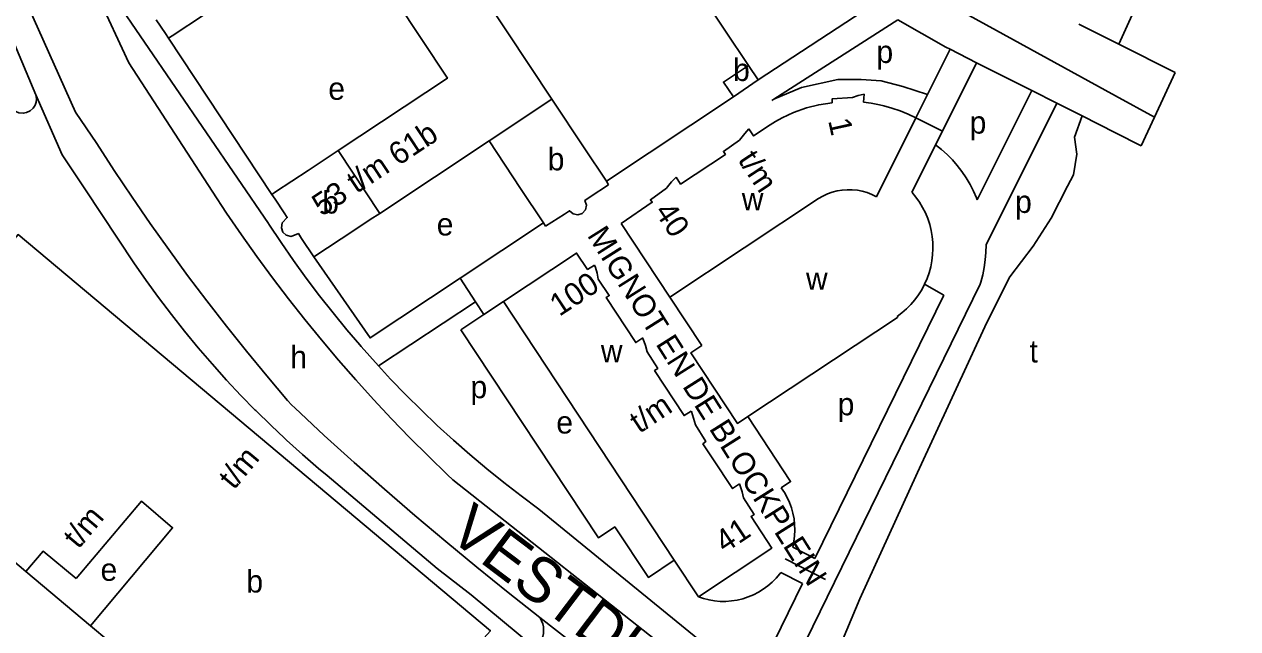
# Model space of a CAD drawing. Extents: x 160673 to 161924, y 382258 to 384145.
# Drawn here: x 161632.6 to 161848.9, y 383061.6 to 383169.3 of the extents above; entities that cross this region are included whole.
import ezdxf

# ---------------------------------------------------------------- set-up
doc = ezdxf.new("R2010")
doc.units = 0
for name, color, linetype in [('BLT_Basislijn', 7, 'Continuous'), ('BLT_Bebouwing', 7, 'Continuous'), ('BLT_Centroide', 7, 'Continuous'), ('BLT_Huisnummer_reeks', 7, 'Continuous'), ('BLT_Onderdoorgang_en_onderverdeling', 7, 'Continuous'), ('BLT_Onderverdeling_panden', 7, 'Continuous'), ('BLT_Straatnaam_hoofdweg', 7, 'Continuous'), ('BLT_Straatnaam_verkleind', 7, 'Continuous'), ('BLT_Vlakafsluiter', 7, 'Continuous')]:
    doc.layers.add(name, color=color, linetype=linetype)

msp = doc.modelspace()

# ---------------------------------------------------------------- linework, layer by layer
at = {"layer": 'BLT_Basislijn'}
for p, q in [((161676.17, 383133.8), (161644.31, 383180.4)), ((161763.41, 383159.38), (161783.67, 383172.63)), ((161766.2, 383155.97), (161788.32, 383170.08)), ((161827.12, 383166.05), (161820.55, 383169.32)), ((161676.76, 383139), (161658.36, 383166.81)), ((161827.69, 383165.77), (161827.12, 383166.05)), ((161793.58, 383156.77), (161797.62, 383164.84)), ((161797.62, 383164.84), (161802.36, 383162.45)), ((161666.12, 383139.57), (161651.29, 383162.43)), ((161796.26, 383150.28), (161802.36, 383162.45)), ((161812.19, 383157.5), (161802.46, 383138.05)), ((161812.19, 383157.5), (161816.65, 383155.25)), ((161634.69, 383156.74), (161639.36, 383146.05)), ((161759.04, 383156.37), (161736.37, 383141.33)), ((161765.85, 383155.74), (161766.2, 383155.97)), ((161791.51, 383152.65), (161793.58, 383156.77)), ((161816.65, 383155.25), (161804.03, 383130)), ((161816.65, 383155.25), (161821.16, 383152.98)), ((161821.16, 383152.98), (161819.83, 383149.18)), ((161821.16, 383152.98), (161827.12, 383149.98)), ((161827.12, 383149.98), (161831.7, 383147.66)), ((161639.36, 383146.05), (161643.52, 383139.82)), ((161643.52, 383139.82), (161652.16, 383126.81)), ((161725.14, 383133.94), (161710.34, 383124.06)), ((161710.34, 383124.06), (161713.07, 383119.87)), ((161802.97, 383122.97), (161766.55, 383048.54)), ((161793.09, 383122.98), (161796.51, 383121.02)), ((161796.51, 383121.02), (161773.53, 383074.14)), ((161695.77, 383108.42), (161713.07, 383119.87)), ((161713.07, 383119.87), (161714.55, 383117.6)), ((161714.55, 383117.6), (161718.02, 383119.89)), ((161710.43, 383114.87), (161714.55, 383117.6)), ((161686.59, 383088.93), (161706.21, 383072.34)), ((161774.99, 383036.07), (161709.02, 383088.14)), ((161762.58, 383051.8), (161724.31, 383082.94)), ((161773.53, 383074.14), (161769.59, 383076.17)), ((161775.42, 383070.36), (161768.26, 383074.05)), ((161632.93, 383071.83), (161644.46, 383062.15)), ((161771.33, 383069.65), (161767.46, 383071.65)), ((161771.33, 383069.65), (161762.58, 383051.8))]:
    msp.add_line(p, q, dxfattribs=at)
for points in [[(161665.14, 383245.7), (161705.82, 383223.19), (161827.12, 383156.57)], [(161846.82, 383218.48), (161848.89, 383212.43), (161827.69, 383165.77)], [(161617.1, 383208.61), (161641.78, 383153.62), (161645.56, 383148.03), (161648.67, 383143.25), (161651.84, 383138.51), (161655.08, 383133.82), (161658.38, 383129.17), (161661.75, 383124.57), (161665.19, 383120.02), (161668.68, 383115.51), (161672.25, 383111.06), (161675.87, 383106.65), (161679.55, 383102.3), (161680.29, 383101.44)], [(161742.19, 383190.52), (161753.26, 383174.57), (161761.69, 383161.98)], [(161651.29, 383162.43), (161645.75, 383174.39), (161644.31, 383180.4)], [(161788.32, 383170.08), (161796.9, 383165.21), (161797.62, 383164.84)], [(161827.69, 383165.77), (161837.77, 383160.71)], [(161802.36, 383162.45), (161812.19, 383157.5)], [(161766.2, 383155.97), (161771.16, 383158.04), (161777.63, 383159.44), (161781.78, 383159.45), (161785.34, 383159.21), (161789.23, 383158.19), (161793.58, 383156.77)], [(161827.12, 383156.57), (161834.07, 383152.75)], [(161819.83, 383149.18), (161820.21, 383146.13), (161819.64, 383142.5), (161818.55, 383140.46), (161815.64, 383134.73), (161812.46, 383129.75), (161808.28, 383124.28), (161804.19, 383116.19), (161791.81, 383089.44), (161781.57, 383066.96), (161775.34, 383052.22)], [(161795.04, 383147.83), (161796.09, 383146.99), (161797.09, 383146.09), (161798.03, 383145.13), (161798.91, 383144.11), (161799.73, 383143.05), (161800.49, 383141.94), (161801.18, 383140.78), (161801.8, 383139.59), (161802.34, 383138.36), (161802.46, 383138.05)], [(161666.12, 383139.57), (161668.7, 383135.64), (161671.35, 383131.76), (161674.07, 383127.93), (161676.85, 383124.14), (161679.7, 383120.4), (161682.61, 383116.71), (161685.58, 383113.07), (161688.61, 383109.48), (161691.7, 383105.94), (161694.86, 383102.45), (161698.07, 383099.02), (161701.34, 383095.65), (161704.67, 383092.33), (161708.05, 383089.06), (161709.02, 383088.14)], [(161692.41, 383112.19), (161690.14, 383114.85), (161687.66, 383117.87), (161685.25, 383120.94), (161682.9, 383124.06), (161680.61, 383127.23), (161678.39, 383130.44), (161676.24, 383133.7), (161676.17, 383133.8)], [(161804.03, 383130), (161804, 383128.66), (161803.89, 383127.32), (161803.7, 383125.98), (161803.44, 383124.67), (161803.09, 383123.37), (161802.97, 383122.97)], [(161684.23, 383127.86), (161694.27, 383113.42), (161710.34, 383124.06)], [(161652.16, 383126.81), (161654.33, 383123.68), (161656.55, 383120.61), (161657.32, 383119.6)], [(161657.32, 383119.6), (161658.85, 383117.58), (161661.21, 383114.6), (161663.62, 383111.67), (161666.11, 383108.79), (161668.68, 383105.91)], [(161748.47, 383073.84), (161743.86, 383070.77), (161737.86, 383079.76), (161734.95, 383077.83), (161710.43, 383114.87)], [(161695.77, 383108.42), (161692.68, 383111.88), (161692.41, 383112.19)], [(161724.31, 383082.94), (161721.18, 383085.27), (161718.09, 383087.66), (161715.05, 383090.12), (161712.06, 383092.63), (161709.13, 383095.21), (161706.24, 383097.84), (161703.42, 383100.54), (161700.65, 383103.29), (161697.93, 383106.1), (161695.77, 383108.42)], [(161668.68, 383105.91), (161671.25, 383103.19), (161673.81, 383100.57)], [(161724.52, 383063.62), (161718.88, 383068.07), (161713.29, 383072.58), (161707.75, 383077.16), (161702.26, 383081.79), (161696.82, 383086.49), (161691.44, 383091.24), (161686.11, 383096.06), (161680.83, 383100.94), (161680.29, 383101.44)], [(161673.81, 383100.57), (161673.9, 383100.47), (161676.62, 383097.81), (161679.02, 383095.56)], [(161761.61, 383099.44), (161769.19, 383087.83), (161767.54, 383086.74)], [(161679.02, 383095.56), (161679.39, 383095.21), (161682.21, 383092.67), (161685.09, 383090.18), (161686.59, 383088.93)], [(161769.59, 383076.17), (161769.8, 383077.16), (161769.92, 383078.17), (161769.97, 383079.17), (161769.93, 383080.18), (161769.82, 383081.19), (161769.63, 383082.18), (161769.36, 383083.15), (161769.01, 383084.1), (161768.59, 383085.02), (161768.1, 383085.9), (161767.54, 383086.74)], [(161723.47, 383058.38), (161712.3, 383067.64), (161706.21, 383072.34)], [(161752.77, 383067.31), (161753.69, 383066.98), (161754.67, 383066.74), (161755.67, 383066.58), (161756.68, 383066.49), (161757.69, 383066.49), (161758.7, 383066.57), (161759.7, 383066.73), (161760.68, 383066.97), (161761.64, 383067.28), (161762.57, 383067.67), (161763.47, 383068.13), (161764.33, 383068.66), (161765.15, 383069.26), (161765.91, 383069.92), (161766.62, 383070.63), (161767.27, 383071.41), (161767.46, 383071.65)], [(161724.11, 383058.83), (161724.56, 383059.31), (161724.83, 383059.69), (161725.03, 383060.23), (161725.15, 383060.79), (161725.19, 383061.36), (161725.15, 383061.94), (161725.03, 383062.5), (161724.83, 383063.04), (161724.52, 383063.62)]]:
    msp.add_lwpolyline(points, dxfattribs=at)
at = {"layer": 'BLT_Bebouwing'}
for p, q in [((161761.69, 383161.98), (161763.41, 383159.38)), ((161763.41, 383159.38), (161759.04, 383156.37)), ((161726.68, 383155.97), (161732.44, 383147.27)), ((161782.17, 383155.43), (161782.3, 383156.82)), ((161715.49, 383148.55), (161695.98, 383135.61)), ((161721.09, 383140.06), (161715.49, 383148.55)), ((161732.44, 383147.27), (161736.37, 383141.33)), ((161795.04, 383147.83), (161792.77, 383143.26)), ((161792.77, 383143.26), (161790.84, 383139.37)), ((161725.14, 383133.94), (161721.09, 383140.06)), ((161736.78, 383140.7), (161733.47, 383138.54)), ((161736.37, 383141.33), (161736.78, 383140.7)), ((161694.29, 383134.49), (161695.98, 383135.61)), ((161725.54, 383133.33), (161725.14, 383133.94)), ((161728.89, 383135.47), (161725.54, 383133.33)), ((161739, 383133.78), (161747.66, 383120.71)), ((161747.66, 383120.71), (161753.36, 383112.08)), ((161748.47, 383073.84), (161718.02, 383119.89)), ((161632.93, 383071.83), (161605.39, 383094.94)), ((161752.77, 383067.31), (161748.47, 383073.84)), ((161682.18, 383030.53), (161644.46, 383062.15))]:
    msp.add_line(p, q, dxfattribs=at)
for points in [[(161692.21, 383207.98), (161709.38, 383182.09), (161709.93, 383182.91), (161711.09, 383183.14), (161712.15, 383182.42), (161712.4, 383181.2), (161711.69, 383180.19), (161710.74, 383180.02), (161726.68, 383155.97)], [(161688.57, 383146.81), (161708.05, 383159.68), (161689.63, 383187.5), (161670.15, 383174.62)], [(161634.69, 383156.74), (161627.93, 383172.69), (161627.23, 383174.06), (161626.42, 383175.36)], [(161670.15, 383174.62), (161664.76, 383171.04), (161658.99, 383167.23), (161658.36, 383166.81)], [(161612.81, 383169.34), (161613.04, 383168.88), (161613.37, 383168.27), (161613.67, 383167.83), (161613.97, 383167.37), (161614.32, 383166.89), (161614.76, 383166.36), (161615.16, 383165.93), (161615.52, 383165.55), (161616.02, 383165.1), (161616.51, 383164.69), (161616.95, 383164.35), (161628.63, 383155.6), (161630.61, 383154.11), (161631.12, 383153.74), (161631.69, 383153.52), (161632.46, 383153.45), (161633.03, 383153.56), (161633.69, 383153.87), (161634.23, 383154.35), (161634.56, 383154.87), (161634.75, 383155.41), (161634.81, 383156.04), (161634.69, 383156.74)], [(161656.15, 383170.1), (161657.79, 383167.68), (161658.36, 383166.81)], [(161759.04, 383156.37), (161757.23, 383159.01), (161761.69, 383161.98)], [(161767.72, 383152.65), (161769.74, 383153.58), (161772.05, 383154.4), (161774.23, 383154.95), (161776.64, 383155.33)], [(161780.21, 383156.25), (161776.6, 383155.99), (161776.64, 383155.33)], [(161782.3, 383156.82), (161781.27, 383156.58), (161780.26, 383156.26), (161780.21, 383156.25)], [(161785.04, 383154.95), (161783.58, 383155.23), (161782.17, 383155.43)], [(161791.51, 383152.65), (161790.13, 383153.29), (161788.72, 383153.86), (161787.27, 383154.35), (161785.81, 383154.76), (161785.04, 383154.95)], [(161765.54, 383151.38), (161762.6, 383149.42), (161761.79, 383150.64)], [(161767.72, 383152.65), (161766.49, 383151.97), (161765.54, 383151.38)], [(161791.51, 383152.65), (161796.26, 383150.28)], [(161761.79, 383150.64), (161761.04, 383149.82), (161760.34, 383148.94), (161760.12, 383148.63)], [(161796.26, 383150.28), (161795.04, 383147.83)], [(161676.76, 383139), (161677.41, 383139.43), (161683.23, 383143.23), (161688.57, 383146.81)], [(161760.12, 383148.63), (161757.24, 383146.66), (161757.6, 383146.12), (161749.61, 383140.84), (161748.8, 383142.06)], [(161747.08, 383140.07), (161744.23, 383138.05), (161744.55, 383137.58), (161739, 383133.78)], [(161748.8, 383142.06), (161748.01, 383141.22), (161747.27, 383140.33), (161747.08, 383140.07)], [(161678.97, 383135.68), (161677.34, 383138.13), (161676.76, 383139)], [(161733.47, 383138.54), (161732.56, 383137.93), (161732.86, 383137.1), (161732.65, 383136.25), (161732.09, 383135.61), (161731.3, 383135.36), (161730.45, 383135.53), (161729.82, 383136.09), (161728.89, 383135.47)], [(161793.09, 383122.98), (161793.53, 383123.98), (161793.89, 383125.01), (161794.18, 383126.07), (161794.39, 383127.14), (161794.52, 383128.22), (161794.58, 383129.32), (161794.55, 383130.41), (161794.44, 383131.5), (161794.25, 383132.57), (161793.99, 383133.63), (161793.65, 383134.67), (161793.23, 383135.68), (161792.74, 383136.66), (161792.18, 383137.6), (161791.55, 383138.49), (161790.86, 383139.34), (161790.84, 383139.37)], [(161682.05, 383131.16), (161681.48, 383132.02), (161680.22, 383131.49), (161679.3, 383131.72), (161678.73, 383132.24), (161678.46, 383133.03), (161678.62, 383133.9), (161679.51, 383134.86), (161678.97, 383135.68)], [(161689.1, 383131.06), (161690.66, 383132.09), (161694.29, 383134.49)], [(161717.99, 383054.63), (161713.37, 383058.5), (161714.56, 383059.91), (161715.72, 383061.26), (161631.52, 383131.82), (161630.38, 383130.44), (161629.19, 383129.01), (161624.8, 383132.69)], [(161682.05, 383131.16), (161684.23, 383127.86)], [(161684.23, 383127.86), (161689.1, 383131.06)], [(161718.02, 383119.89), (161731.07, 383128.53), (161733.04, 383125.62), (161734.26, 383126.41)], [(161734.93, 383123.9), (161734.72, 383124.93), (161734.42, 383125.94), (161734.26, 383126.41)], [(161734.93, 383123.9), (161736.88, 383120.97), (161736.33, 383120.61), (161741.62, 383112.6), (161742.85, 383113.42)], [(161788.18, 383117.22), (161789.05, 383117.88), (161789.87, 383118.6), (161790.64, 383119.38), (161791.35, 383120.21), (161792, 383121.09), (161792.58, 383122.01), (161793.09, 383122.98)], [(161788.18, 383117.22), (161788.26, 383117.07), (161761.61, 383099.44)], [(161743.64, 383110.95), (161743.33, 383112.07), (161742.95, 383113.18), (161742.85, 383113.42)], [(161761.61, 383099.44), (161759.72, 383098.19), (161751.41, 383110.76), (161753.36, 383112.08)], [(161743.64, 383110.95), (161745.52, 383107.98), (161744.98, 383107.6), (161750.23, 383099.59), (161751.48, 383100.39)], [(161752.23, 383097.91), (161751.91, 383099.11), (161751.52, 383100.3), (161751.48, 383100.39)], [(161752.23, 383097.91), (161754.11, 383094.98), (161753.58, 383094.54), (161755.35, 383091.88)], [(161755.35, 383091.88), (161758.86, 383086.58), (161760.09, 383087.41)], [(161760.84, 383084.91), (161760.56, 383086.01), (161760.21, 383087.08), (161760.09, 383087.41)], [(161644.46, 383062.15), (161659.08, 383079.61), (161653.52, 383084.32), (161641.9, 383070.55)], [(161760.84, 383084.91), (161762.7, 383081.95), (161762.17, 383081.63), (161765.86, 383075.99), (161752.77, 383067.31)], [(161641.9, 383070.55), (161635.99, 383075.43), (161632.93, 383071.83)]]:
    msp.add_lwpolyline(points, dxfattribs=at)
at = {"layer": 'BLT_Onderdoorgang_en_onderverdeling'}
for p, q in [((161715.49, 383148.55), (161726.68, 383155.97)), ((161695.98, 383135.61), (161688.57, 383146.81))]:
    msp.add_line(p, q, dxfattribs=at)
at = {"layer": 'BLT_Onderverdeling_panden'}
for p, q in [((161784.51, 383138.58), (161791.51, 383152.65)), ((161747.66, 383120.71), (161774.2, 383138.26))]:
    msp.add_line(p, q, dxfattribs=at)
msp.add_lwpolyline([(161784.51, 383138.58), (161783.7, 383138.98), (161782.86, 383139.3), (161781.99, 383139.55), (161781.1, 383139.72), (161780.2, 383139.81), (161779.29, 383139.82), (161778.39, 383139.75), (161777.5, 383139.6), (161776.62, 383139.37), (161775.77, 383139.07), (161774.95, 383138.69), (161774.2, 383138.26)], dxfattribs=at)
at = {"layer": 'BLT_Vlakafsluiter'}
msp.add_line((161724.52, 383063.62), (161737.11, 383053.84), dxfattribs=at)
msp.add_lwpolyline([(161837.77, 383160.71), (161834.07, 383152.75), (161831.7, 383147.66)], dxfattribs=at)

# ---------------------------------------------------------------- texts
at = {"layer": 'BLT_Centroide'}
for s, p in [('p', (161784.51, 383162.4)), ('b', (161758.96, 383159.19)), ('e', (161686.82, 383155.84)), ('p', (161801.11, 383149.82)), ('b', (161725.92, 383143.28)), ('b', (161685.74, 383135.58)), ('w', (161760.51, 383136.17)), ('p', (161809.22, 383135.69)), ('e', (161706.14, 383131.67)), ('w', (161771.95, 383122)), ('h', (161680.05, 383108.03)), ('w', (161735.39, 383109.09)), ('t', (161811.79, 383109.05)), ('p', (161712.16, 383102.68)), ('p', (161777.59, 383099.64)), ('e', (161727.45, 383096.39)), ('e', (161646.23, 383070.15)), ('b', (161672.22, 383068.07))]:
    msp.add_text(s, height=4, dxfattribs=at).set_placement(p)
at = {"layer": 'BLT_Huisnummer_reeks'}
for s, rotation, p in [('53 t/m 61b', 33.4993, (161685.64, 383134.95)), ('1 ', 282.4602, (161775.88, 383152.14)), ('t/m', 303.5148, (161759.7, 383145.14)), ('40', 303.5148, (161744.83, 383135.93)), ('100', 33.4993, (161728, 383117.15)), ('t/m', 33.5332, (161742.25, 383096.32)), ('t/m', 50.0162, (161669.99, 383086.23)), ('t/m', 50.0162, (161642.29, 383075.68)), ('41 ', 33.5332, (161757.46, 383075))]:
    msp.add_text(s, height=4, rotation=rotation, dxfattribs=at).set_placement(p)
at = {"layer": 'BLT_Straatnaam_hoofdweg'}
msp.add_text('VESTDIJK', height=8, rotation=322.9152, dxfattribs=at).set_placement((161707.87, 383077.97))
at = {"layer": 'BLT_Straatnaam_verkleind'}
msp.add_text('MIGNOT EN DE BLOCKPLEIN', height=4, rotation=302.2592, dxfattribs=at).set_placement((161732.85, 383131.7))

doc.saveas('drawing.dxf')
